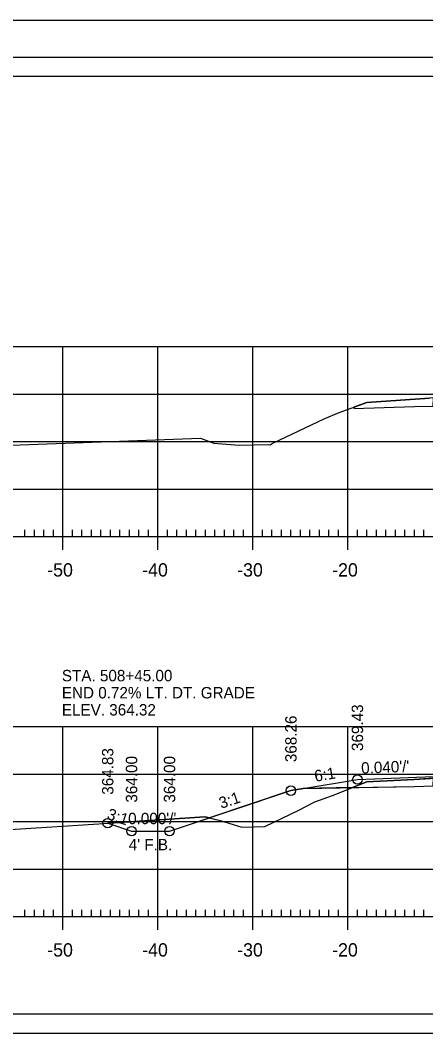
# Model space of a CAD drawing. Extents: x 1368910 to 1369601, y 380116 to 380950.
# Drawn here: x 1369025.7 to 1369068.4, y 380630.4 to 380737.1 of the extents above; entities that cross this region are included whole.
import ezdxf

# ---------------------------------------------------------------- set-up
doc = ezdxf.new("R2010")
doc.units = 0
for name, color, linetype in [('_STAGE 2 CUT', 7, 'Continuous'), ('_STAGE 2 FILL', 7, 'Continuous'), ('Notes', 7, 'Continuous'), ('R_Alt Surface', 7, 'Continuous'), ('R_Axis', 7, 'Continuous'), ('R_Axis Annot', 7, 'Continuous'), ('R_Border', 7, 'Continuous'), ('R_Border Plan-Plan', 7, 'Continuous'), ('R_Exist Surface', 7, 'Continuous'), ('R_Fin Surface', 7, 'Continuous'), ('R_Grid', 7, 'Continuous'), ('R_No Plot', 7, 'Continuous'), ('R_Xsect Elev', 7, 'Continuous'), ('R_Xsect Slope', 7, 'Continuous')]:
    doc.layers.add(name, color=color, linetype=linetype)

msp = doc.modelspace()

# ---------------------------------------------------------------- linework, layer by layer
at = {"layer": '_STAGE 2 CUT'}
for p, q in [((1369060.95, 380696.42), (1369060.88, 380696.25)), ((1369060.72, 380656.34), (1369067.24, 380656.47)), ((1369045.66, 380653.16), (1369045.16, 380653.28))]:
    msp.add_line(p, q, dxfattribs=at)
for points in [[(1369060.88, 380696.25), (1369067.24, 380696.46), (1369069.23, 380696.5), (1369069.24, 380697.33), (1369080.24, 380697.55)], [(1369080.09, 380697.72), (1369075.66, 380697.55), (1369075.58, 380697.54), (1369075.44, 380697.54), (1369069.62, 380697.38), (1369069.59, 380697.38), (1369069.38, 380697.37), (1369068.82, 380697.33), (1369062.24, 380696.88), (1369060.95, 380696.42)], [(1369069.24, 380657.33), (1369067.22, 380657.2), (1369062.25, 380656.95), (1369060.72, 380656.34)], [(1369067.24, 380656.47), (1369069.23, 380656.51), (1369069.24, 380657.33)], [(1369045.16, 380653.28), (1369035.11, 380652.6), (1369034.95, 380652.59)], [(1369034.95, 380652.59), (1369037.46, 380651.76), (1369041.46, 380651.76), (1369045.66, 380653.16)]]:
    msp.add_lwpolyline(points, dxfattribs=at)
at = {"layer": '_STAGE 2 FILL'}
msp.add_line((1369060.72, 380656.34), (1369055.52, 380656.23), dxfattribs=at)
for points in [[(1369045.66, 380653.16), (1369046.79, 380652.87), (1369049.07, 380652.18), (1369050.38, 380652.22), (1369051.49, 380652.23), (1369055.08, 380653.98), (1369056.75, 380654.85), (1369058.63, 380655.5), (1369060.72, 380656.34)], [(1369055.52, 380656.23), (1369054.24, 380656.02), (1369045.66, 380653.16)]]:
    msp.add_lwpolyline(points, dxfattribs=at)
at = {"layer": 'R_Alt Surface'}
msp.add_lwpolyline([(1369055.52, 380656.23), (1369067.24, 380656.47), (1369069.23, 380656.51), (1369069.24, 380657.34), (1369080.24, 380657.56), (1369091.24, 380657.34), (1369091.25, 380656.51), (1369093.24, 380656.47), (1369104.97, 380656.23)], dxfattribs=at)
at = {"layer": 'R_Axis'}
for p, q in [((1369030.24, 380681.36), (1369030.24, 380684.16)), ((1369040.24, 380681.36), (1369040.24, 380684.16)), ((1369050.24, 380681.36), (1369050.24, 380684.16)), ((1369060.24, 380681.36), (1369060.24, 380684.16)), ((1368940.24, 380682.76), (1369220.24, 380682.76)), ((1369026.24, 380682.76), (1369026.24, 380683.46)), ((1369027.24, 380682.76), (1369027.24, 380683.46)), ((1369028.24, 380682.76), (1369028.24, 380683.46)), ((1369029.24, 380682.76), (1369029.24, 380683.46)), ((1369031.24, 380682.76), (1369031.24, 380683.46)), ((1369032.24, 380682.76), (1369032.24, 380683.46)), ((1369033.24, 380682.76), (1369033.24, 380683.46)), ((1369034.24, 380682.76), (1369034.24, 380683.46)), ((1369035.24, 380682.76), (1369035.24, 380683.46)), ((1369036.24, 380682.76), (1369036.24, 380683.46)), ((1369037.24, 380682.76), (1369037.24, 380683.46)), ((1369038.24, 380682.76), (1369038.24, 380683.46)), ((1369039.24, 380682.76), (1369039.24, 380683.46)), ((1369041.24, 380682.76), (1369041.24, 380683.46)), ((1369042.24, 380682.76), (1369042.24, 380683.46)), ((1369043.24, 380682.76), (1369043.24, 380683.46)), ((1369044.24, 380682.76), (1369044.24, 380683.46)), ((1369045.24, 380682.76), (1369045.24, 380683.46)), ((1369046.24, 380682.76), (1369046.24, 380683.46)), ((1369047.24, 380682.76), (1369047.24, 380683.46)), ((1369048.24, 380682.76), (1369048.24, 380683.46)), ((1369049.24, 380682.76), (1369049.24, 380683.46)), ((1369051.24, 380682.76), (1369051.24, 380683.46)), ((1369052.24, 380682.76), (1369052.24, 380683.46)), ((1369053.24, 380682.76), (1369053.24, 380683.46)), ((1369054.24, 380682.76), (1369054.24, 380683.46)), ((1369055.24, 380682.76), (1369055.24, 380683.46)), ((1369056.24, 380682.76), (1369056.24, 380683.46)), ((1369057.24, 380682.76), (1369057.24, 380683.46)), ((1369058.24, 380682.76), (1369058.24, 380683.46)), ((1369059.24, 380682.76), (1369059.24, 380683.46)), ((1369061.24, 380682.76), (1369061.24, 380683.46)), ((1369062.24, 380682.76), (1369062.24, 380683.46)), ((1369063.24, 380682.76), (1369063.24, 380683.46)), ((1369064.24, 380682.76), (1369064.24, 380683.46)), ((1369065.24, 380682.76), (1369065.24, 380683.46)), ((1369066.24, 380682.76), (1369066.24, 380683.46)), ((1369067.24, 380682.76), (1369067.24, 380683.46)), ((1369068.24, 380682.76), (1369068.24, 380683.46)), ((1369030.24, 380641.36), (1369030.24, 380644.16)), ((1369040.24, 380641.36), (1369040.24, 380644.16)), ((1369050.24, 380641.36), (1369050.24, 380644.16)), ((1369060.24, 380641.36), (1369060.24, 380644.16)), ((1369026.24, 380642.76), (1369026.24, 380643.46)), ((1369027.24, 380642.76), (1369027.24, 380643.46)), ((1369028.24, 380642.76), (1369028.24, 380643.46)), ((1369029.24, 380642.76), (1369029.24, 380643.46)), ((1369031.24, 380642.76), (1369031.24, 380643.46)), ((1369032.24, 380642.76), (1369032.24, 380643.46)), ((1369033.24, 380642.76), (1369033.24, 380643.46)), ((1369034.24, 380642.76), (1369034.24, 380643.46)), ((1369035.24, 380642.76), (1369035.24, 380643.46)), ((1369036.24, 380642.76), (1369036.24, 380643.46)), ((1369037.24, 380642.76), (1369037.24, 380643.46)), ((1369038.24, 380642.76), (1369038.24, 380643.46)), ((1369039.24, 380642.76), (1369039.24, 380643.46)), ((1369041.24, 380642.76), (1369041.24, 380643.46)), ((1369042.24, 380642.76), (1369042.24, 380643.46)), ((1369043.24, 380642.76), (1369043.24, 380643.46)), ((1369044.24, 380642.76), (1369044.24, 380643.46)), ((1369045.24, 380642.76), (1369045.24, 380643.46)), ((1369046.24, 380642.76), (1369046.24, 380643.46)), ((1369047.24, 380642.76), (1369047.24, 380643.46)), ((1369048.24, 380642.76), (1369048.24, 380643.46)), ((1369049.24, 380642.76), (1369049.24, 380643.46)), ((1369051.24, 380642.76), (1369051.24, 380643.46)), ((1369052.24, 380642.76), (1369052.24, 380643.46)), ((1369053.24, 380642.76), (1369053.24, 380643.46)), ((1369054.24, 380642.76), (1369054.24, 380643.46)), ((1369055.24, 380642.76), (1369055.24, 380643.46)), ((1369056.24, 380642.76), (1369056.24, 380643.46)), ((1369057.24, 380642.76), (1369057.24, 380643.46)), ((1369058.24, 380642.76), (1369058.24, 380643.46)), ((1369059.24, 380642.76), (1369059.24, 380643.46)), ((1369061.24, 380642.76), (1369061.24, 380643.46)), ((1369062.24, 380642.76), (1369062.24, 380643.46)), ((1369063.24, 380642.76), (1369063.24, 380643.46)), ((1369064.24, 380642.76), (1369064.24, 380643.46)), ((1369065.24, 380642.76), (1369065.24, 380643.46)), ((1369066.24, 380642.76), (1369066.24, 380643.46)), ((1369067.24, 380642.76), (1369067.24, 380643.46)), ((1369068.24, 380642.76), (1369068.24, 380643.46)), ((1368940.24, 380642.76), (1369220.24, 380642.76))]:
    msp.add_line(p, q, dxfattribs=at)
at = {"layer": 'R_Border'}
msp.add_line((1368922.24, 380733.22), (1369238.42, 380733.22), dxfattribs=at)
at = {"layer": 'R_Border Plan-Plan'}
msp.add_line((1368922.24, 380630.49), (1369238.42, 380630.49), dxfattribs=at)
at = {"layer": 'R_Exist Surface'}
for points in [[(1369022.84, 380692.31), (1369044.73, 380693.14), (1369046.14, 380692.6), (1369048.78, 380692.38), (1369051.91, 380692.44), (1369052.07, 380692.43), (1369052.27, 380692.55), (1369057.8, 380695.21), (1369059.31, 380695.83), (1369062.24, 380696.88), (1369068.82, 380697.33)], [(1369019.68, 380651.63), (1369035.11, 380652.6), (1369045.16, 380653.28), (1369046.79, 380652.87), (1369049.07, 380652.18), (1369050.38, 380652.22), (1369051.49, 380652.23), (1369055.08, 380653.98), (1369056.75, 380654.85), (1369058.63, 380655.5), (1369062.25, 380656.95), (1369067.22, 380657.2), (1369069.54, 380657.35)]]:
    msp.add_lwpolyline(points, dxfattribs=at)
at = {"layer": 'R_Fin Surface'}
msp.add_lwpolyline([(1369034.95, 380652.59), (1369037.46, 380651.76), (1369041.46, 380651.76), (1369054.24, 380656.02), (1369055.52, 380656.23), (1369061.24, 380657.19), (1369069.24, 380657.51), (1369080.24, 380657.73), (1369091.24, 380657.51), (1369099.24, 380657.19), (1369104.97, 380656.23), (1369106.24, 380656.02), (1369118.26, 380652.01)], dxfattribs=at)
at = {"layer": 'R_Grid'}
for p, q in [((1368940.24, 380702.76), (1369220.24, 380702.76)), ((1369030.24, 380682.76), (1369030.24, 380702.76)), ((1369040.24, 380682.76), (1369040.24, 380702.76)), ((1369050.24, 380682.76), (1369050.24, 380702.76)), ((1369060.24, 380682.76), (1369060.24, 380702.76)), ((1368940.24, 380697.76), (1369220.24, 380697.76)), ((1368940.24, 380692.76), (1369220.24, 380692.76)), ((1368940.24, 380687.76), (1369220.24, 380687.76)), ((1368940.24, 380682.76), (1369220.24, 380682.76)), ((1368940.24, 380662.76), (1369220.24, 380662.76)), ((1369030.24, 380642.76), (1369030.24, 380662.76)), ((1369040.24, 380642.76), (1369040.24, 380662.76)), ((1369050.24, 380642.76), (1369050.24, 380662.76)), ((1369060.24, 380642.76), (1369060.24, 380662.76)), ((1368940.24, 380657.76), (1369220.24, 380657.76)), ((1368940.24, 380652.76), (1369220.24, 380652.76)), ((1368940.24, 380647.76), (1369220.24, 380647.76)), ((1368940.24, 380642.76), (1369220.24, 380642.76))]:
    msp.add_line(p, q, dxfattribs=at)
at = {"layer": 'R_No Plot'}
for points in [[(1368909.84, 380737.11), (1369243.18, 380737.11), (1369243.18, 380523.78), (1368909.84, 380523.78)], [(1369236.42, 380632.49), (1368924.24, 380632.49), (1368924.24, 380731.22), (1369173.78, 380731.22), (1369173.78, 380721.34), (1369191.32, 380721.34), (1369215.42, 380721.34), (1369215.42, 380699.01), (1369236.42, 380699.01)], [(1368924.24, 380731.22), (1369173.78, 380731.22), (1369173.78, 380721.34), (1369191.32, 380721.34), (1369215.42, 380721.34), (1369215.42, 380699.01), (1369236.42, 380699.01), (1369236.42, 380529.76), (1368924.24, 380529.76)]]:
    msp.add_lwpolyline(points, close=True, dxfattribs=at)
for centre in [(1369061.24, 380657.19), (1369054.24, 380656.02), (1369034.95, 380652.59), (1369037.46, 380651.76), (1369041.46, 380651.76)]:
    msp.add_circle(centre, 0.5, dxfattribs=at)

# ---------------------------------------------------------------- texts
at = {"layer": 'Notes'}
for s, p in [('STA. 508+45.00', (1369030.12, 380667.53)), ('END 0.72% LT. DT. GRADE', (1369030.12, 380665.73)), ('ELEV. 364.32', (1369030.12, 380663.93))]:
    msp.add_text(s, height=1.2, dxfattribs=at).set_placement(p)
at = {"layer": 'R_Axis Annot'}
for s, p in [('-50', (1369028.58, 380678.56)), ('-40', (1369038.58, 380678.56)), ('-30', (1369048.58, 380678.56)), ('-20', (1369058.58, 380678.56)), ('-50', (1369028.58, 380638.56)), ('-40', (1369038.58, 380638.56)), ('-30', (1369048.58, 380638.56)), ('-20', (1369058.58, 380638.56))]:
    msp.add_text(s, height=1.4, dxfattribs=at).set_placement(p)
at = {"layer": 'R_Xsect Elev'}
for s, p in [('369.43', (1369061.84, 380660.19)), ('368.26', (1369054.84, 380659.02)), ('364.83', (1369035.55, 380655.59)), ('364.00', (1369038.06, 380654.76)), ('364.00', (1369042.06, 380654.76))]:
    msp.add_text(s, height=1.2, rotation=90, dxfattribs=at).set_placement(p)
at = {"layer": 'R_Xsect Slope'}
for s, rotation, p in [("0.040'/'", 2.2906, (1369061.66, 380657.8)), ('6:1', 9.4623, (1369056.81, 380656.95)), ('3:1', 18.4349, (1369046.9, 380654.1)), ('3:1', 341.5651, (1369034.78, 380653.06)), ("0.000'/'", 360, (1369037.1, 380652.49)), ("4' F.B.", 360, (1369037.16, 380649.74))]:
    msp.add_text(s, height=1.2, rotation=rotation, dxfattribs=at).set_placement(p)

doc.saveas('drawing.dxf')
